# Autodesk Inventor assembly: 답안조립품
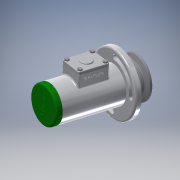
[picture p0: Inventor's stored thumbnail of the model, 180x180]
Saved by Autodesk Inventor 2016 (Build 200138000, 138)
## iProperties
Created: 2017-05
Part Number: 답안조립품
Material: 일반
Document SubType Name: Assembly
Designer: USER
Author: USER
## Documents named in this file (18)
- C:\Users\USER\Desktop\470508V1017\답안조립품.iam
- C:\Users\USER\Desktop\470508V1017\V-벨트풀리.ipt
- C:\Users\USER\Desktop\470508V1017\너트 M10.ipt
- C:\Users\USER\Desktop\470508V1017\멈춤링 15 x 1.ipt
- C:\Users\USER\Desktop\470508V1017\멈춤링 35x1.6.ipt
- C:\Users\USER\Desktop\470508V1017\베어링 15 x 35 x 11.ipt
- C:\Users\USER\Desktop\470508V1017\본체.ipt
- C:\Users\USER\Desktop\470508V1017\볼트 M4 x 10.ipt
- C:\Users\USER\Desktop\470508V1017\부시1.ipt
- C:\Users\USER\Desktop\470508V1017\부시2.ipt
- C:\Users\USER\Desktop\470508V1017\사이드 커버.ipt
- 사이드 커버.ipt
- C:\Users\USER\Desktop\470508V1017\십자볼트 M3 x 10.ipt
- C:\Users\USER\Desktop\470508V1017\와셔 3x6.ipt
- C:\Users\USER\Desktop\470508V1017\와셔 4x16.ipt
- C:\Users\USER\Desktop\470508V1017\축.ipt
- C:\Users\USER\Desktop\470508V1017\키 4 x 4 x 18.ipt
- C:\Users\USER\Desktop\470508V1017\탑 커버.ipt
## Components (5 placed, 2 different names)
1. V-벨트풀리:1
2. ISO 4017 M4 x 10:1
3. ISO 4017 M4 x 10:2
4. ISO 4017 M4 x 10:3
5. ISO 4017 M4 x 10:4
